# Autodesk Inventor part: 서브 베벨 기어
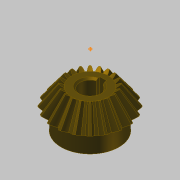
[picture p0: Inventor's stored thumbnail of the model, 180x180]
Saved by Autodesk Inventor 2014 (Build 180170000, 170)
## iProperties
Created: 2016-04
Part Number: 서브 베벨 기어
Material: 강철, 탄소
Document SubType Name: Modeling
Designer: mdu
Categories: <?xml version="1.0" encoding="UTF-16"?> <MemberInstance><Categories><FamilyTemplate><FamilyTemplateParameter ValueType="xs:double" Id="1" ObjectReferenceKey="da
Mass: 135.037 g
Surface Area: 63.6518 cm^2
Volume: 17.1585 cm^3
Density: 7.87 g/cm^3
Appearance: 얼룩무늬
CustomPartVersion: 1
Author: mdu
Revision Number: 1
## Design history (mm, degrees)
node "맨 위 점"
node "메쉬 평면2"
sketch "톱니 본체 스케치"
  geometry: L1 (0, 0)-(18.003, -31.331); L2 (18.003, -31.331)-(21.664, -28.891); L3 (21.664, -28.891)-(0, 0); L4 (20, -30)-(0, 0); L5 (10.813, -18.818)-(13.012, -17.352); L6 (18.003, -31.331)-(10.813, -18.818); L7 (21.664, -28.891)-(13.012, -17.352); L8 (0, -39.387)-(0, 6.564) reference; L9 (0, -30)-(21.664, -30)
  constraints: 16 end point, 4 point on line, 3 perpendicular, 2 collinear, 1 horizontal alignment, 1 vertical alignment
  dimensions: "d0" = 40 diameter of L4.start L8 (= da_de); "d1" = 36.00616 diameter of L1.end L8 (= da_dfe); "d2" = 43.3282 diameter of L2.end L8 (= da_dae); "d3" = 14.4 distance between parallel lines of L2 L5 (= da_b); "d4" = 28.8906 vertical distance of L2.end L1.start (= da_ve)
revolve "톱니 본체" sketch "톱니 본체 스케치" stored, may be unused: angle "d5" = 90 deg
node "시작점"
node "톱니 평면"
sketch "시작 스케치"
  geometry: L1 (0, -23.505)-(0, 10.645) reference; L2 (-0.834, -2.928)-(0.834, -2.928); A1 r 8.898 centre (-9.698, -3.713) between (-0.834, -2.928) and (-3.903, 3.04); A2 r 8.898 centre (9.698, -3.713) between (3.903, 3.04) and (0.834, -2.928); A3 r 27.357 centre (0, -24.037) between (3.903, 3.04) and (-3.903, 3.04); 1 further point
  constraints: 6 point on circle, 3 centre point, 3 symmetric about line, 2 end point, 1 coincident, 1 perpendicular, 1 other
  dimensions: "d7" = 8.89846 radius of A1 (= fd_rr); "d8" = 9.69794 horizontal distance of point (0, -24.037) A1.centre (= fd_x); "d9" = 20.32439 vertical distance of point (0, -24.037) A1.centre (= fd_y); "d57" = 27.35701 radius of A3 (= 0.5 x fd_dva + 0.3 x da_he); "d58" = 21.10901 distance from line of A3.centre L2 (= 0.5 x fd_dva - 1.12 x da_he)
node "끝점"
  node "끝 평면"
sketch "3D 스케치 오른쪽"
  node "Helical Curve Right" dims "d65" = 229.90621 (computed from da_dm, da_delta, da_beta), "d66" = 31.5, "d67" = 40 (= da_de), "d68" = -5.88003 (= -da_delta), "d69" = 12.16458 (computed from fd_loft, da_delta)
node "끝 평면 오른쪽"
sketch "끝 스케치 오른쪽"
  geometry: L1 (0, -22.649)-(0, 12.15) reference; L2 (-0.497, -1.72)-(0.497, -1.72); A1 r 5.299 centre (-5.775, -2.187) between (-0.497, -1.72) and (-2.324, 1.834); A2 r 5.299 centre (5.775, -2.187) between (2.324, 1.834) and (0.497, -1.72); A3 r 16.291 centre (0, -14.29) between (2.324, 1.834) and (-2.324, 1.834); 1 further point
  constraints: 6 point on circle, 3 centre point, 3 symmetric about line, 2 end point, 1 coincident, 1 perpendicular, 1 other
  dimensions: "d70" = 5.77526 horizontal distance of A3.centre A1.centre (computed from fd_x, fd_ratio); "d71" = 12.10346 vertical distance of point (0, -14.29) A1.centre (computed from fd_y, fd_ratio); "d72" = 5.29916 radius of A1 (computed from fd_rr, fd_ratio); "d73" = 12.57071 distance from line of point (0, -14.29) L2 (computed from d58, fd_ratio); "d74" = 16.29149 radius of A3 (computed from d57, fd_ratio)
feature "로프트 오른쪽" sketch "끝 스케치 오른쪽" dims "d75" = 0, "d77" = 0, "d79" = 0, "d80" = 90 deg, "d85" = 20, "d92" = 90 deg, "d93" = 90 deg, "da_teethtype" = 0 [user parameter]
sketch "3D 스케치 왼쪽"
  node "Helical Curve Left" dims "d26" = 229.90621 (computed from da_dm, da_delta, da_beta), "d27" = 12.16458 (computed from fd_loft, da_delta), "d28" = 40 (= da_de), "d29" = -5.88003 (= -da_delta)
node "끝 평면 왼쪽"
sketch "끝 스케치 왼쪽" dims "d56" = 10.82768 (derived)
  geometry: L1 (0, -35.087)-(0, 18.089) reference; L2 (-0.497, -1.716)-(0.497, -1.716); A1 r 5.299 centre (-5.775, -2.183) between (-0.497, -1.716) and (-2.324, 1.838); A2 r 5.299 centre (5.775, -2.183) between (2.324, 1.838) and (0.497, -1.716); A3 r 16.291 centre (0, -14.287) between (2.324, 1.838) and (-2.324, 1.838); 2 further points; 1 other entity
  constraints: 6 point on circle, 3 centre point, 3 symmetric about line, 2 end point, 1 coincident, 2 other
  dimensions: "d30" = 5.29916 radius of A1 (computed from fd_rr, fd_ratio); "d31" = 5.77526 horizontal distance of point (0, -14.287) A1.centre (computed from fd_x, fd_ratio); "d32" = 12.10346 vertical distance of A1.centre point (0, -14.287) (computed from fd_y, fd_ratio); "d61" = 16.29149 radius of A3 (computed from d57, fd_ratio); "d62" = 12.57071 distance from line of point (0, -14.287) L2 (computed from d58, fd_ratio)
feature "로프트 왼쪽" sketch "끝 스케치 왼쪽" dims "d35" = 0, "d37" = 0, "d39" = 0, "d40" = 90 deg, "d84" = 10, "d90" = 90 deg, "d91" = 90 deg, "da_teethtype" = 0 [user parameter]
sketch "본체 스케치"
  geometry: L1 (0, -35.038)-(0, -19.531) reference; L2 (18.003, -31.331)-(10.813, -18.818) reference; L3 (10.813, -18.818)-(0, -18.818); L4 (18.003, -31.331)-(0, -31.331)
  constraints: 4 end point, 2 perpendicular, 2 point on line
revolve "본체 고정" sketch "본체 스케치" stored, may be unused: angle "d46" = 90 deg
feature "피치 지름" dims angle "d47" = 90 deg
sketch "스케치8"
  geometry: C1 r 17 at (0, 0); 1 further point
  constraints: 1 centre point, 1 coincident
  dimensions: "d94" = 34 diameter of C1
extrude "돌출1" join sketch "스케치8" distance "d95" = 10; taper "d96" = 0 deg
sketch "스케치9"
  geometry: 1 further point
hole "구멍1" sketch "스케치9" at (0, 0) diameter "d97" = 12; stored, may be unused: countersink angle "d101" = 90 deg, drill point angle "d103" = 118 deg; dims "d98" = 6, "d99" = 4, "d100" = 2, "d102" = 8
sketch "스케치10"
  geometry: 1 further point
sketch "스케치11"
  geometry: 1 further point
sketch "스케치12"
  geometry: L1 (-2, 5.657)-(-2, 7.8); L2 (-2, 7.8)-(2, 7.8); L3 (2, 7.8)-(2, 5.657); A1 r 6 centre (0, 0) between (-2, 5.657) and (2, 5.657) reference; 1 further point
  constraints: 6 end point, 2 parallel, 2 point on circle, 1 perpendicular, 1 vertical
  dimensions: "d104" = 4 distance of L1.end L2.end; "d105" = 13.8 dimension on A1 L2
extrude "돌출2" cut sketch "스케치12" stored distance "d106" = 7; taper "d107" = 0 deg
chamfer "모따기1" distance "d108" = 1; stored, may be unused: second distance "d109" = 2, angle "d110" = 45 deg
body "Solid1"
feature "로프트" dims "d17" = 0, "d18" = 90 deg, "d19" = 0, "d20" = 90 deg, "d89" = 0, "da_teethtype" = 0 [user parameter]
pattern_circular "원형 패턴" dims angle "d22" = 360 deg, "d88" = 0, "da_teethtype" = 0 [user parameter]
pattern_circular "원형 패턴 오른쪽" dims angle "d82" = 360 deg, "da_teethtype" = 0 [user parameter]
pattern_circular "원형 패턴 왼쪽" dims angle "d42" = 360 deg, "da_teethtype" = 0 [user parameter]
sketch "끝 스케치"
  geometry: L1 (0, -15.359)-(0, 6.983) reference; L2 (-0.497, -1.72)-(0.497, -1.72); A1 r 5.299 centre (-5.775, -2.187) between (-0.497, -1.72) and (-2.324, 1.834); A2 r 5.299 centre (5.775, -2.187) between (2.324, 1.834) and (0.497, -1.72); A3 r 16.291 centre (0, -14.29) between (2.324, 1.834) and (-2.324, 1.834); 1 further point
  constraints: 6 point on circle, 3 centre point, 3 symmetric about line, 2 end point, 1 coincident, 1 other
  dimensions: "d12" = 5.29916 radius of A1 (computed from fd_rr, fd_ratio); "d15" = 5.77526 horizontal distance of A1.centre point (0, -14.29) (computed from fd_x, fd_ratio); "d16" = 12.10346 vertical distance of A1.centre point (0, -14.29) (computed from fd_y, fd_ratio); "d59" = 16.29149 radius of A3 (computed from d57, fd_ratio); "d60" = 12.57071 distance from line of A3.centre L2 (computed from d58, fd_ratio)
sketch "Sketch6"
  geometry: L1 (20, -30)-(0, 0) reference; L2 (0, -37.8)-(0, 6.3) reference
body "Srf1"
other parameters: "da_b" = 14.4 [user parameter; used in 2 equation terms], "da_de" = 40 [user parameter; used in 4 equation terms], "da_dae" = 43.3282 [user parameter; used in 2 equation terms], "da_dfe" = 36.00616 [user parameter; used in 1 equation term], "da_le" = 36.05551 [user parameter; used in 1 equation term], "da_omega" = 90 deg [user parameter; used in 1 equation term], "da_beta" = 0 [user parameter; used in 2 equation terms], "da_delta" = 5.88003 [user parameter; used in 8 equation terms], "da_alpha" = 20 deg [user parameter; used in 2 equation terms], "da_he" = 4.4 [user parameter; used in 4 equation terms], "da_ve" = 28.8906 [user parameter; used in 1 equation term], "fd_dv" = 48.07402 (computed from da_de, da_delta) [user parameter; used in 1 equation term], "fd_dva" = 52.07402 (computed from da_dae, da_delta) [user parameter; used in 3 equation terms], "fd_dvb" = 45.1748 (computed from fd_dv, da_alpha) [user parameter; used in 2 equation terms], "da_zv" = 240.37008 [user parameter; used in 1 equation term], "fd_loft" = 14.62 (= da_b + 0.05 x da_he) [user parameter; used in 4 equation terms], "fd_ratio" = 5.95514 (computed from da_le, fd_loft) [user parameter; used in 15 equation terms], "fd_rr" = 8.89846 (computed from fd_dd, fd_dvb) [user parameter; used in 6 equation terms], "fd_angle" = 0.66075 (computed from da_zv) [user parameter; used in 4 equation terms], "fd_x1" = 1.58709 (computed from da_dvw, fd_angle) [user parameter; used in 1 equation term], "fd_y1" = 23.98456 (computed from da_dvw, fd_angle) [user parameter; used in 1 equation term], "fd_x2" = 8.11084 (computed from fd_rr, fd_angle2, fd_angle) [user parameter; used in 1 equation term], "fd_y2" = 3.66016 (computed from fd_rr, fd_angle2, fd_angle) [user parameter; used in 1 equation term], "fd_x" = 9.69794 (= fd_x1 + fd_x2) [user parameter; used in 4 equation terms], "fd_y" = 20.32439 (= fd_y1 - fd_y2) [user parameter; used in 4 equation terms], "fd_angle2" = 3.57832 (computed from fd_dvb, fd_dd, da_alpha) [user parameter; used in 2 equation terms], "fd_dd" = 48.55402 (= fd_dva - 0.8 x da_he) [user parameter; used in 2 equation terms], "da_dvw" = 48.07402 [user parameter; used in 2 equation terms], "d11" = 14.62 (= fd_loft), "da_dm" = 32.01232 [user parameter; used in 2 equation terms], "da_x" = 0 [user parameter], "da_m" = 2 [user parameter], "d48" = 0, "d49" = 0, "d50" = 90 deg (= da_omega), "d51" = 9 deg (computed from da_z), "d52" = 0, "d53" = 0, "d54" = 0
